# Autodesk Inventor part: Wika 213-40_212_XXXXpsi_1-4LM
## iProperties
Author: ARennick
Shininess: 64.0
Angle Display Precision: 2
Document Length Units: 11272
Document Angle Units: 11286
Document Time Units: 11279
Document Mass Units: 11290
Document Length Units Precision: 3
Document Angle Units Precision: 2
Compacted: True
PropertySet Name: _Private Model Information
Created: 2002-04
Part Number: Wika 213-40_212_XXXXpsi_1-4LM
Catalog Web Link: www.wika.com
Description: Pressure Gauge, Liquid Filled, 2.5in Face, XXXXpsi, 1/4NPT, LM, No Flange
Vendor: Motion Industries
Document SubType Name: Modeling
Designer: ARennick
Control State: 0
Master: False
Checked Out: False
PropertySet Name: Design Tracking Control
Density: 0.0
Volumn: 0.0
Area: 0.0
PropertySet Name: Model Information
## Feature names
1. Revolution2
2. Hole1
3. NoFlange [Extrusion]
4. Extrusion2
5. Extrusion4
6. Pointer [Extrusion]
7. PointerShaft [Extrusion]
8. TickMarks [Extrusion]
9. Circular Pattern1
10. Extrusion7
11. Fillet1
12. CBMSquare [Extrusion]
13. CBMPipe [Extrusion]
14. LMPipe [Extrusion]
15. LMSquare [Extrusion]
